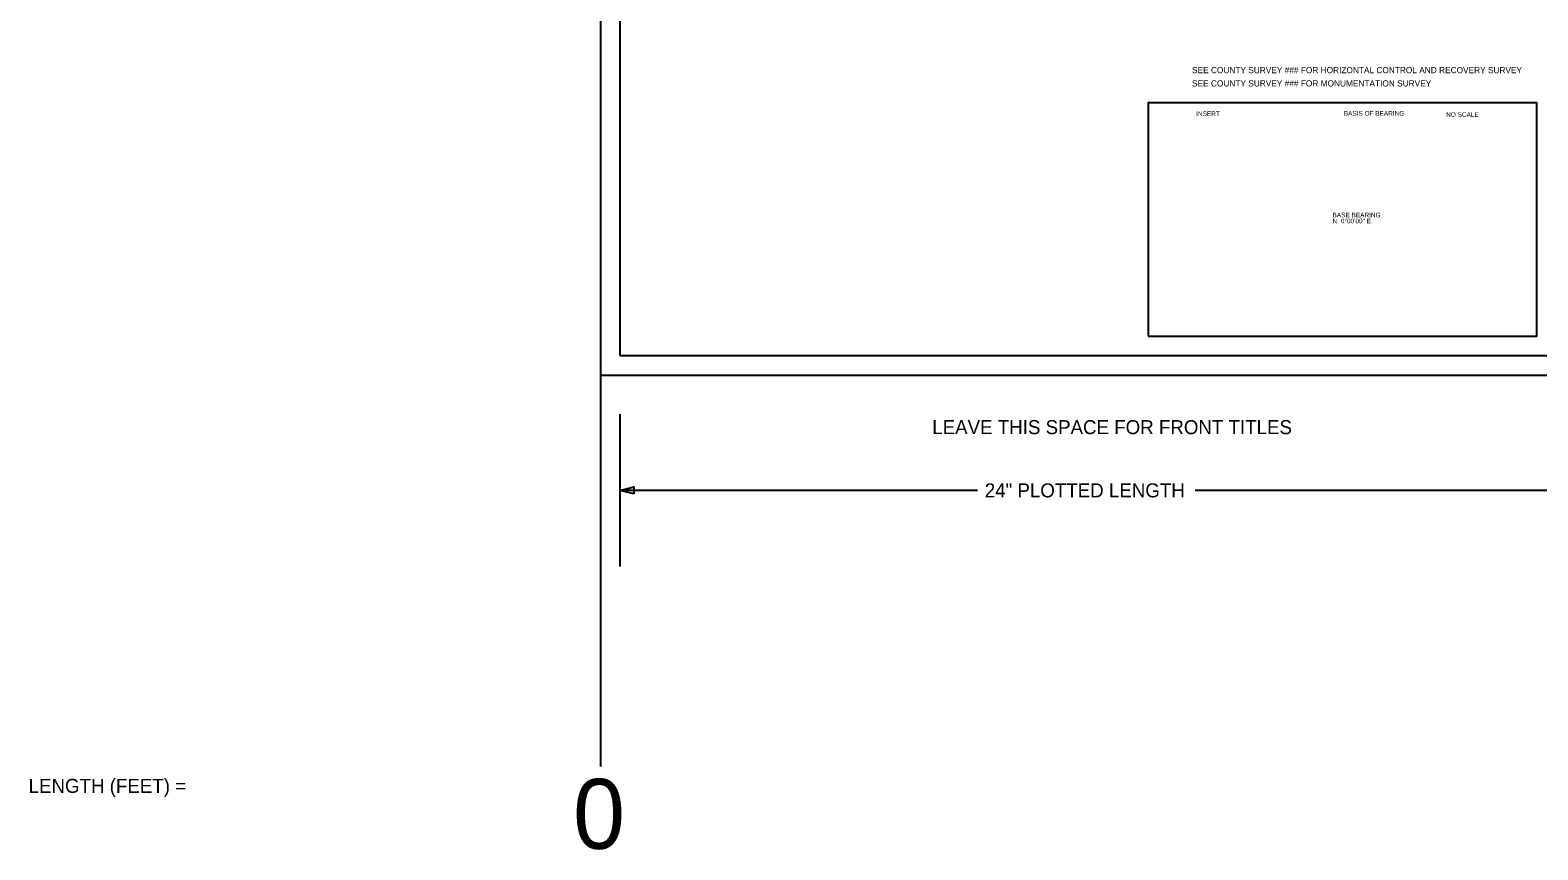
# Model space of a CAD drawing. Extents: x -1.2 to 17.3, y -1 to 2.5.
# Drawn here: x -1.223 to 2.01, y -1.018 to 0.739 of the extents above; entities that cross this region are included whole.
import ezdxf

# ---------------------------------------------------------------- set-up
doc = ezdxf.new("R2010")
doc.units = 0
for name, color, linetype in [('#plot_shape', 7, 'Continuous'), ('P_ODOT_PLAN_Border', 7, 'Continuous'), ('P_ODOT_PLAN_General', 7, 'Continuous')]:
    doc.layers.add(name, color=color, linetype=linetype)

msp = doc.modelspace()

# ---------------------------------------------------------------- linework, layer by layer
at = {"layer": '#plot_shape'}
msp.add_lwpolyline([(0, 0), (16.6667, 0), (16.6667, 2), (0, 2)], close=True, dxfattribs=at)
msp.add_lwpolyline([(0, 0), (16.6667, 0), (16.6667, 2), (0, 2)], close=True, dxfattribs=at)
at = {"layer": 'P_ODOT_PLAN_Border'}
for points in [[(0.0417, 0.0417), (16.625, 0.0417), (16.625, 1.9583), (0.0417, 1.9583)], [(0.0417, 0.0417), (16.625, 0.0417), (16.625, 1.9583), (0.0417, 1.9583)], [(1.1742, 0.0836), (2.0076, 0.0836), (2.0076, 0.5836), (1.1742, 0.5836)], [(1.1742, 0.0836), (2.0076, 0.0836), (2.0076, 0.5836), (1.1742, 0.5836)], [(1.1742, 0.0836), (2.0076, 0.0836), (2.0076, 0.5836), (1.1742, 0.5836)], [(1.1742, 0.0836), (2.0076, 0.0836), (2.0076, 0.5836), (1.1742, 0.5836)]]:
    msp.add_lwpolyline(points, close=True, dxfattribs=at)
at = {"layer": 'P_ODOT_PLAN_General'}
for p, q in [((0, 0), (0, -0.8389)), ((0, 0), (0, -0.8389)), ((0.0417, -0.0839), (0.0417, -0.4104)), ((0.0417, -0.0839), (0.0417, -0.4104)), ((0.8086, -0.2471), (0.0417, -0.2471)), ((0.8086, -0.2471), (0.0417, -0.2471)), ((2.0419, -0.2471), (1.275, -0.2471)), ((2.0419, -0.2471), (1.275, -0.2471))]:
    msp.add_line(p, q, dxfattribs=at)
msp.add_lwpolyline([(0.0717, -0.2546), (0.0417, -0.2471), (0.0717, -0.2396)], close=True, dxfattribs=at)
msp.add_lwpolyline([(0.0717, -0.2546), (0.0417, -0.2471), (0.0717, -0.2396)], close=True, dxfattribs=at)

# ---------------------------------------------------------------- texts
for s, height, p in [('SEE COUNTY SURVEY ### FOR HORIZONTAL CONTROL AND RECOVERY SURVEY', 0.0133, (1.2683, 0.6471)), ('SEE COUNTY SURVEY ### FOR HORIZONTAL CONTROL AND RECOVERY SURVEY', 0.0133, (1.2683, 0.6471)), ('SEE COUNTY SURVEY ### FOR MONUMENTATION SURVEY', 0.0133, (1.2683, 0.6186)), ('SEE COUNTY SURVEY ### FOR MONUMENTATION SURVEY', 0.0133, (1.2683, 0.6186)), ('INSERT', 0.01, (1.2773, 0.5551)), ('INSERT', 0.01, (1.2773, 0.5551)), ('BASIS OF BEARING', 0.01, (1.5937, 0.556)), ('BASIS OF BEARING', 0.01, (1.5937, 0.556)), ('NO SCALE', 0.01, (1.8132, 0.5534)), ('NO SCALE', 0.01, (1.8132, 0.5534)), ('BASE BEARING', 0.01, (1.5697, 0.3381)), ('BASE BEARING', 0.01, (1.5697, 0.3381)), ('N. 0°00\'00" E.', 0.01, (1.5697, 0.3253)), ('N. 0°00\'00" E.', 0.01, (1.5697, 0.3253)), ('LEAVE THIS SPACE FOR FRONT TITLES', 0.03, (0.7113, -0.1266)), ('LEAVE THIS SPACE FOR FRONT TITLES', 0.03, (0.7113, -0.1266)), ('24" PLOTTED LENGTH', 0.03, (0.8239, -0.2621)), ('24" PLOTTED LENGTH', 0.03, (0.8239, -0.2621)), ('LENGTH (FEET) =', 0.03, (-1.2262, -0.8955)), ('LENGTH (FEET) =', 0.03, (-1.2262, -0.8955)), ('0', 0.15, (-0.0589, -1.0155)), ('0', 0.15, (-0.0589, -1.0155))]:
    msp.add_text(s, height=height, dxfattribs=at).set_placement(p)

doc.saveas('drawing.dxf')
